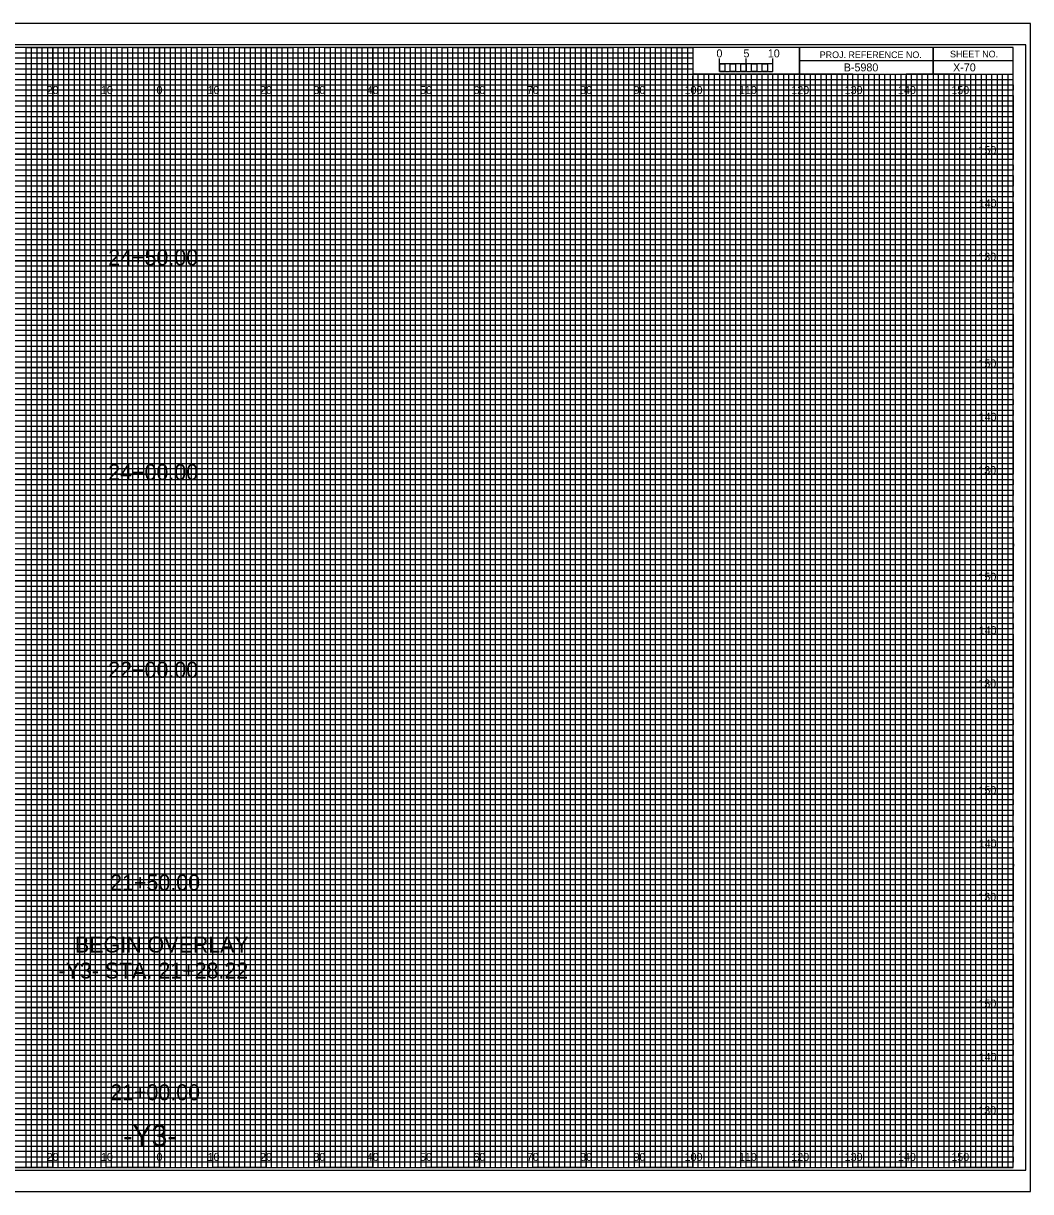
# Model space of a CAD drawing. Extents: x -13 to 323, y -5 to 434.
# Drawn here: x 134.5 to 323.3, y -4.5 to 214.5 of the extents above; entities that cross this region are included whole.
import ezdxf

# ---------------------------------------------------------------- set-up
doc = ezdxf.new("R2010")
doc.units = 0
for name, color, linetype in [('Exist Cross Section Cell', 7, 'Continuous'), ('Exist XS Center Line Elevation Label', 7, 'Continuous'), ('Exist XS Ground Line', 7, 'Continuous'), ('Prop CMT Pvmt Course 1', 7, 'Continuous'), ('Prop CMT Pvmt Course 2', 7, 'Continuous'), ('Prop CMT Pvmt Course 3', 7, 'Continuous'), ('Prop CMT Pvmt Surface', 7, 'Continuous'), ('Prop CMT Pvmt Surface Shoulder', 7, 'Continuous'), ('Prop CMT Shld Paved Course 1', 7, 'Continuous'), ('Prop CMT Shld Paved Course 2', 7, 'Continuous'), ('Prop CMT Shld Paved Course 3', 7, 'Continuous'), ('Prop CMT Slope Grass', 7, 'Continuous'), ('Prop CMT Subgrade Earthwork', 7, 'Continuous'), ('Prop SS Cut Text', 7, 'Continuous'), ('Prop SS Fill Line', 7, 'Continuous'), ('Prop SS Transition Line', 7, 'Continuous'), ('Prop XS Side Slope Text', 7, 'Continuous')]:
    doc.layers.add(name, color=color, linetype=linetype)

msp = doc.modelspace()

# ---------------------------------------------------------------- linework, layer by layer
at = {"layer": 'Exist XS Center Line Elevation Label'}
for points in [[(125, 0), (135, 0), (135, 210), (145, 210), (145, 0), (155, 0), (155, 210), (165, 210), (165, 0), (175, 0), (175, 210), (185, 210), (185, 0), (195, 0), (195, 210), (205, 210), (205, 0), (215, 0), (215, 210), (225, 210), (225, 0), (235, 0), (235, 210), (245, 210), (245, 0), (255, 0), (255, 210), (259.93, 210), (260, 210), (260, 205), (264.99, 205), (264.99, 0), (275, 0), (275, 205), (285, 205), (285, 0), (295, 0), (295, 205), (305, 205), (305, 0), (315, 0), (315, 205)], [(0, 205), (275, 205)], [(0, 185), (320, 185), (320, 195), (0, 195)], [(0, 165), (320, 165), (320, 175), (0, 175)], [(0, 145), (320, 145), (320, 155), (0, 155)], [(0, 125), (320, 125), (320, 135), (0, 135)], [(0, 105), (320, 105), (320, 115), (0, 115)], [(0, 85), (320, 85), (320, 95), (0, 95)], [(0, 65), (320, 65), (320, 75), (0, 75)], [(0, 45), (320, 45), (320, 55), (0, 55)], [(0, 25), (320, 25), (320, 35), (0, 35)], [(0, 5), (320, 5), (320, 15), (0, 15)]]:
    msp.add_lwpolyline(points, dxfattribs=at)
at = {"layer": 'Exist XS Ground Line'}
for p, q in [((150, 210), (140, 210)), ((140, 210), (140, 0)), ((150, 0), (150, 210)), ((170, 210), (160, 210)), ((160, 210), (160, 0)), ((170, 0), (170, 210)), ((190, 210), (180, 210)), ((180, 210), (180, 0)), ((190, 0), (190, 210)), ((210, 210), (200, 210)), ((200, 210), (200, 0)), ((210, 0), (210, 210)), ((230, 210), (220, 210)), ((220, 210), (220, 0)), ((230, 0), (230, 210)), ((250, 210), (240, 210)), ((240, 210), (240, 0)), ((250, 0), (250, 210)), ((260, 210), (260, 0)), ((270, 0), (270, 205)), ((290, 205), (280, 205)), ((280, 205), (280, 0)), ((290, 0), (290, 205)), ((310, 205), (300, 205)), ((300, 205), (300, 0)), ((310, 0), (310, 205)), ((140, 0), (130, 0)), ((160, 0), (150, 0)), ((180, 0), (170, 0)), ((200, 0), (190, 0)), ((220, 0), (210, 0)), ((240, 0), (230, 0)), ((260, 0), (250, 0)), ((280, 0), (270, 0)), ((300, 0), (290, 0)), ((320, 0), (310, 0)), ((320, 0), (320, 0))]:
    msp.add_line(p, q, dxfattribs=at)
for points in [[(0, 200), (320, 200), (320, 190), (0, 190)], [(0, 180), (320, 180), (320, 170), (0, 170)], [(0, 160), (320, 160), (320, 150), (0, 150)], [(0, 140), (320, 140), (320, 130), (0, 130)], [(0, 120), (320, 120), (320, 110), (0, 110)], [(0, 100), (320, 100), (320, 90), (0, 90)], [(0, 80), (320, 80), (320, 70), (0, 70)], [(0, 60), (320, 60), (320, 50), (0, 50)], [(0, 40), (320, 40), (320, 30), (0, 30)], [(0, 20), (320, 20), (320, 10), (0, 10)]]:
    msp.add_lwpolyline(points, dxfattribs=at)
at = {"layer": 'Prop CMT Pvmt Course 1'}
for p, q in [((265, 205.49), (265, 207.9)), ((265, 206.9), (265, 207.9)), ((270, 205.49), (270, 207.9)), ((275, 205.49), (275, 207.9)), ((275, 206.9), (275, 207.9))]:
    msp.add_line(p, q, dxfattribs=at)
for points in [[(275, 206.9), (265, 206.9), (265, 205.49), (275, 205.49)], [(265, 206.9), (266, 206.9), (266, 205.49), (265, 205.49)], [(267, 206.9), (268, 206.9), (268, 205.49), (267, 205.49)], [(269, 206.9), (270, 206.9), (270, 205.49), (269, 205.49)], [(271, 206.9), (272, 206.9), (272, 205.49), (271, 205.49)], [(273, 206.9), (274, 206.9), (274, 205.49), (273, 205.49)]]:
    msp.add_lwpolyline(points, close=True, dxfattribs=at)
at = {"layer": 'Prop CMT Pvmt Course 2'}
for p, q in [((0, 209), (260, 209)), ((260, 209), (260, 207.98)), ((260, 207.98), (0, 207.98)), ((0, 207), (260, 207)), ((260, 205.89), (0, 205.89)), ((260, 207), (260, 205.89)), ((0, 204), (320, 204))]:
    msp.add_line(p, q, dxfattribs=at)
for points in [[(0, 203), (270, 203), (320, 203), (320, 202), (0, 202)], [(0, 201), (320, 201), (320, 199), (0, 199)], [(0, 198), (320, 198), (320, 197), (0, 196.98)], [(0, 196), (320, 196), (320, 194), (0, 194)], [(0, 193), (320, 193), (320, 192), (0, 192)], [(0, 191), (320, 191), (320, 189), (0, 189)], [(0, 188), (320, 188), (320, 187), (0, 187)], [(0, 186), (320, 186), (320, 184), (0, 184)], [(0, 183), (320, 183), (320, 182), (0, 182)], [(0, 181), (320, 181), (320, 179), (0, 179)], [(0, 178), (320, 178), (320, 177), (0, 177)], [(0, 176), (320, 176), (320, 173.95), (320, 173), (320, 172), (0, 172)], [(0, 174), (320, 174), (320, 173), (0, 173)], [(0, 171), (320, 171), (320, 169), (0, 169.03)], [(0, 169.03), (320, 169), (320, 168), (0, 168)], [(0, 167), (320, 167), (320, 166), (0, 166)], [(0, 164), (320, 164), (320, 163), (0, 163)], [(0, 162), (320, 162), (320, 161), (0, 161)], [(-0.07, 158.89), (320, 158.89), (320, 157.88), (-0.07, 157.88)], [(0, 157), (320, 157), (320, 156), (0, 156)], [(0, 154), (320, 154), (320, 153), (0, 153)], [(0, 152), (320, 152), (320, 151), (0, 151)], [(0, 149), (320, 149), (320, 148), (0, 148)], [(0, 147), (320, 147), (320, 146), (0, 146)], [(0, 144), (320, 144), (320, 143), (0, 143)], [(0, 142), (320, 142), (320, 141), (0, 141)], [(0, 139), (320, 139), (319.99, 137.98), (0, 138)], [(0, 137), (320, 137), (320, 136), (0, 136)], [(0, 134), (320, 134), (320, 133), (0, 133)], [(0, 132), (320, 132), (320, 131), (0, 131)], [(0, 129), (320, 129), (320, 128), (0, 128)], [(0, 127), (320, 127), (320, 126), (0, 126)], [(0, 124), (320, 124), (320, 123), (0, 123)], [(0, 122), (320, 122), (320, 121), (0, 121)], [(0, 119), (320, 119), (320, 118), (0, 118)], [(0, 116.99), (320.07, 116.91), (320, 116), (0, 116)], [(0, 114), (320, 114), (320, 113), (0, 113)], [(0, 112), (320, 112), (320, 111), (0, 111)], [(0, 109), (320, 109), (320, 108), (0, 108)], [(0, 107), (320, 107), (320, 106), (0, 106)], [(0, 104), (320, 104), (320, 103), (0, 103)], [(0, 102), (320, 102), (320, 101), (0, 101)], [(0, 99), (320, 99), (320, 98), (0, 98)], [(0, 97), (320, 97), (320, 96), (0, 96)], [(0, 94), (320, 94), (320, 93), (0, 93)], [(0, 92), (320, 92), (320, 91), (0, 91)], [(0, 89), (320, 89), (320, 88), (0, 88)], [(0, 87), (320, 87), (320, 86), (0, 86)], [(0, 84), (320, 84), (320, 83), (0, 83)], [(0, 82), (320, 82), (320, 81), (0, 81)], [(0, 79), (320, 79), (319.99, 77.98), (0, 78)], [(0, 77), (320, 77), (320, 76), (0, 76)], [(0, 74), (320, 74), (320, 73), (0, 73)], [(0, 72), (320, 72), (320, 71), (0, 71)], [(0, 69), (320, 69), (320, 68), (0, 68)], [(0, 67), (320, 67), (320, 66), (0, 66)], [(0, 64), (320, 64), (320, 63), (0, 63)], [(0, 62), (320, 62), (320, 61), (0, 61)], [(0, 59), (320, 59), (320, 58), (0, 58)], [(0, 56.99), (320.07, 56.91), (320, 56), (0, 56)], [(0, 54), (320, 54), (320, 53), (0, 53)], [(0, 52), (320, 52), (320, 51), (0, 51)], [(0, 49), (320, 49), (320, 48), (0, 48)], [(0, 47), (320, 47), (320, 46), (0, 46)], [(0, 44), (320, 44), (320, 43), (0, 43)], [(0, 42), (320, 42), (320, 41), (0, 41)], [(0, 39), (320, 39), (320, 38), (0, 38)], [(0, 37), (320, 37), (320, 36), (0, 36)], [(0, 34), (320, 34), (320, 33), (0, 33)], [(0, 32), (320, 32), (320, 31), (0, 31)], [(0, 29), (320, 29), (320, 28), (0, 28)], [(0, 27), (320, 27), (320, 26), (0, 26)], [(0, 24), (320, 24), (320, 23), (0, 23)], [(0, 22), (320, 22), (320, 21), (0, 21)], [(0, 19), (320, 19), (320, 18), (0, 18)], [(0, 17), (320, 17), (320, 16), (0, 16)], [(0, 14), (320, 14), (320, 13), (0, 13)], [(0, 12), (320, 12), (320, 11), (0, 11)], [(0, 9), (320, 9), (320, 8), (0, 8)], [(0, 7), (320, 7), (320, 6), (0, 6)], [(0, 4), (320, 4), (320, 3), (0, 3)], [(0, 2), (320, 2), (320, 1), (0, 1)]]:
    msp.add_lwpolyline(points, dxfattribs=at)
at = {"layer": 'Prop CMT Pvmt Course 3'}
for p, q in [((305, 210), (305, 205)), ((305, 205), (305, 210)), ((280, 207.5), (280, 205)), ((320, 207.49), (280, 207.49)), ((280, 205), (320, 205))]:
    msp.add_line(p, q, dxfattribs=at)
for points in [[(320, 210), (0, 210), (0, 0), (320, 0)], [(280, 210), (260, 210), (260, 205.03), (280, 205.03)], [(320, 210), (280, 210), (280, 205), (320, 205)]]:
    msp.add_lwpolyline(points, close=True, dxfattribs=at)
at = {"layer": 'Prop CMT Pvmt Surface'}
for p, q in [((267, 205), (266.01, 205)), ((266.01, 205), (266.01, 0)), ((267, 0), (267, 205)), ((269, 205), (268, 205)), ((268, 205), (268, 0)), ((269, 0), (269, 205)), ((266.01, 0), (265, 0)), ((268, 0), (267, 0))]:
    msp.add_line(p, q, dxfattribs=at)
for points in [[(135, 0), (136, 0), (136, 210), (137, 210), (137, 0)], [(137, 0), (138, 0), (138, 210), (139, 210), (139, 0)], [(140, 0), (141, 0), (141, 210), (142, 210), (142, 0)], [(142, 0), (143, 0), (143, 210), (144, 210), (144, 0)], [(145, 0), (146, 0), (146, 210), (147, 210), (147, 0)], [(147, 0), (148, 0), (148, 210), (149, 210), (149, 0)], [(150, 0), (151, 0), (151, 210), (152, 210), (152, 0)], [(152, 0), (153, 0), (153, 210), (154, 210), (154, 0)], [(155, 0), (156, 0), (156, 210), (157, 210), (157, 0)], [(157, 0), (158, 0), (158, 210), (159, 210), (159, 0)], [(160, 0), (161, 0), (161, 210), (162, 210), (162, 0)], [(162, 0), (163, 0), (163, 210), (164, 210), (164, 0)], [(165, 0), (166, 0), (166, 210), (167, 210), (167, 0)], [(167, 0), (168, 0), (168, 210), (169, 210), (169, 0)], [(170, 0), (171, 0), (171, 210), (172, 210), (172, 0)], [(172, 0), (173, 0), (173, 210), (174, 210), (174, 0)], [(175, 0), (176, 0), (176, 210), (177, 210), (177, 0)], [(177, 0), (178, 0), (178, 210), (179, 210), (179, 0)], [(180, 0), (181, 0), (181, 210), (182, 210), (182, 0)], [(182, 0), (183, 0), (183, 210), (184, 210), (184, 0)], [(185, 0), (186, 0), (186, 210), (187, 210), (187, 0)], [(187, 0), (188, 0), (188, 210), (189, 210), (189, 0)], [(190, 0), (191, 0), (191, 210), (192, 210), (192, 0)], [(192, 0), (193, 0), (193, 210), (194, 210), (194, 0)], [(195, 0), (196, 0), (196, 210), (197, 210), (197, 0)], [(197, 0), (198, 0), (198, 210), (199, 210), (199, 0)], [(200, 0), (201, 0), (201, 210), (202, 210), (202, 0)], [(202, 0), (203, 0), (203, 210), (204, 210), (204, 0)], [(205, 0), (206, 0), (206, 210), (207, 210), (207, 0)], [(207, 0), (208, 0), (208, 210), (209, 210), (209, 0)], [(210, 0), (211, 0), (211, 210), (212, 210), (212, 0)], [(212, 0), (213, 0), (213, 210), (214, 210), (214, 0)], [(215, 0), (216, 0), (216, 210), (217, 210), (217, 0)], [(217, 0), (218, 0), (218, 210), (219, 210), (219, 0)], [(220, 0), (221, 0), (221, 210), (222, 210), (222, 0)], [(222, 0), (223, 0), (223, 210), (224, 210), (224, 0)], [(225, 0), (226, 0), (226, 210), (227, 210), (227, 0)], [(227, 0), (228, 0), (228, 210), (229, 210), (229, 0)], [(230, 0), (231, 0), (231, 210), (232, 210), (232, 0)], [(232, 0), (233, 0), (233, 210), (234, 210), (234, 0)], [(235, 0), (236, 0), (236, 210), (237, 210), (237, 0)], [(237, 0), (238, 0), (238, 210), (239, 210), (239, 0)], [(240, 0), (241, 0), (241, 210), (242, 210), (242, 0)], [(242, 0), (243, 0), (243, 210), (244, 210), (244, 0)], [(245, 0), (246, 0), (246, 210), (247, 210), (247, 0)], [(247, 0), (248, 0), (248, 210), (249, 210), (249, 0)], [(250, 0), (251, 0), (251, 210), (252, 210), (252, 0)], [(252, 0), (253, 0), (253, 210), (254, 210), (254, 0)], [(255, 0), (256, 0), (256, 210), (257, 210), (257, 0)], [(257, 0), (258, 0), (258, 210), (259, 210), (259, 0)], [(260, 0), (261, 0), (261, 205), (262.02, 205), (262.02, 0)], [(262, 0), (263, 0), (263, 205), (263.99, 205), (263.99, 0)], [(270, 0), (270.98, 0), (270.98, 205), (272, 205), (272, 0)], [(272, 0), (273, 0), (273, 205), (274.05, 205), (274.05, 0)], [(275, 0), (276, 0), (276, 205), (277, 205), (277, 0)], [(277, 0), (278, 0), (278, 205), (279, 205), (279, 0)], [(280, 0), (281, 0), (281, 205), (282, 205), (282, 0)], [(282, 0), (283, 0), (283, 205), (284, 205), (284, 0)], [(285, 0), (286, 0), (286, 205), (287, 205), (287, 0)], [(287, 0), (288, 0), (288, 205), (289, 205), (289, 0)], [(290, 0), (291, 0), (291, 205), (292, 205), (292, 0)], [(292, 0), (293, 0), (293, 205), (294, 205), (294, 0)], [(295, 0), (296, 0), (296, 205), (297, 205), (297, 0)], [(297, 0), (298, 0), (298, 205), (299, 205), (299, 0)], [(300, 0), (301, 0), (301, 205), (302, 205), (302, 0)], [(302, 0), (303, 0), (303, 205), (304, 205), (304, 0)], [(305, 0), (306, 0), (306, 205), (307, 205), (307, 0)], [(307, 0), (308, 0), (308, 205), (309, 205), (309, 0)], [(310, 0), (311, 0), (311, 205), (312, 205), (312, 0)], [(312, 0), (313, 0), (313, 205), (314, 205), (314, 0)], [(315, 0), (316, 0), (316, 205), (317, 205), (317, 0)], [(317, 0), (318, 0), (318, 205), (319, 205), (319, 0)]]:
    msp.add_lwpolyline(points, dxfattribs=at)
at = {"layer": 'Prop CMT Pvmt Surface Shoulder'}
msp.add_lwpolyline([(-10.8, -0.5), (322.4, -0.5), (322.4, 210.5), (-10.8, 210.5)], close=True, dxfattribs=at)
at = {"layer": 'Prop CMT Shld Paved Course 1'}
for p, q in [((140, 0), (140, 210)), ((150, 0), (150, 210)), ((160, 0), (160, 210)), ((170, 0), (170, 210)), ((180, 0), (180, 210)), ((190, 0), (190, 210)), ((200, 0), (200, 210)), ((210, 0), (210, 210)), ((220, 0), (220, 210)), ((230, 0), (230, 210)), ((240, 0), (240, 210)), ((250, 0), (250, 210)), ((260, 0), (260, 204.69)), ((270, 0), (270, 204.69)), ((280, 0), (280, 204.69)), ((290, 0), (290, 204.69)), ((300, 0), (300, 204.69)), ((310, 0), (310, 204.69)), ((0, 200), (320, 200)), ((0, 190), (320, 190)), ((0, 180), (320, 180)), ((0, 170), (320, 170)), ((0, 160), (320, 160)), ((0, 150), (320, 150)), ((0, 140), (320, 140)), ((0, 130), (320, 130)), ((0, 120), (320, 120)), ((0, 110), (320, 110)), ((0, 100), (320, 100)), ((0, 90), (320, 90)), ((0, 80), (320, 80)), ((0, 70), (320, 70)), ((0, 60), (320, 60)), ((0, 50), (320, 50)), ((0, 40), (320, 40)), ((0, 30), (320, 30)), ((0, 20), (320, 20)), ((0, 10), (320, 10))]:
    msp.add_line(p, q, dxfattribs=at)
at = {"layer": 'Prop CMT Shld Paved Course 2'}
for p, q in [((323.3, 214.5), (-13.4, 214.5)), ((-13.4, -4.5), (323.3, -4.5))]:
    msp.add_line(p, q, dxfattribs=at)
at = {"layer": 'Prop CMT Subgrade Earthwork'}
msp.add_lwpolyline([(-13.4, -4.5), (323.3, -4.5), (323.3, 214.5), (-13.4, 214.5)], close=True, dxfattribs=at)

# ---------------------------------------------------------------- texts
at = {"layer": 'Exist Cross Section Cell'}
for s, p in [('20', (138.86, 201.25)), ('10', (149.04, 201.25)), ('0', (159.45, 201.25)), ('0', (159.45, 201.25)), ('10', (169.04, 201.25)), ('20', (178.86, 201.25)), ('30', (188.86, 201.25)), ('40', (198.86, 201.25)), ('50', (208.86, 201.25)), ('60', (218.86, 201.25)), ('70', (228.86, 201.25)), ('80', (238.86, 201.25)), ('90', (248.86, 201.25)), ('100', (258.44, 201.25)), ('110', (268.62, 201.25)), ('120', (278.44, 201.25)), ('130', (288.44, 201.25)), ('140', (298.44, 201.25)), ('150', (308.44, 201.25)), ('20', (138.86, 1.25)), ('10', (149.04, 1.25)), ('0', (159.45, 1.25)), ('0', (159.45, 1.25)), ('10', (169.04, 1.25)), ('20', (178.86, 1.25)), ('30', (188.86, 1.25)), ('40', (198.86, 1.25)), ('50', (208.86, 1.25)), ('60', (218.86, 1.25)), ('70', (228.86, 1.25)), ('80', (238.86, 1.25)), ('90', (248.86, 1.25)), ('100', (258.44, 1.25)), ('110', (268.62, 1.25)), ('120', (278.44, 1.25)), ('130', (288.44, 1.25)), ('140', (298.44, 1.25)), ('150', (308.44, 1.25))]:
    msp.add_text(s, height=1.5, dxfattribs=at).set_placement(p)
at = {"layer": 'Prop CMT Pvmt Course 1'}
msp.add_text('0', height=1.5, dxfattribs=at).set_placement((264.41, 208.12))
at = {"layer": 'Prop CMT Pvmt Course 3'}
for s, p in [('PROJ. REFERENCE NO.', (283.77, 207.99)), ('SHEET NO.', (308.19, 208.12))]:
    msp.add_text(s, height=1.25, dxfattribs=at).set_placement(p)
at = {"layer": 'Prop CMT Shld Paved Course 3'}
for s, p in [('150', (313.52, 190)), ('140', (313.57, 180)), ('130', (313.49, 170)), ('150', (313.52, 150)), ('140', (313.57, 140)), ('130', (313.49, 130)), ('150', (313.52, 110)), ('140', (313.57, 100)), ('130', (313.49, 90)), ('150', (313.52, 70)), ('140', (313.57, 60)), ('130', (313.49, 50)), ('150', (313.52, 30)), ('140', (313.57, 20)), ('130', (313.49, 10))]:
    msp.add_text(s, height=1.5, dxfattribs=at).set_placement(p)
at = {"layer": 'Prop CMT Slope Grass'}
for s, p in [('24+50.00', (150.41, 169.13)), ('24+00.00', (150.41, 128.88)), ('22+00.00', (150.41, 91.83)), ('21+50.00', (150.77, 51.95)), ('BEGIN OVERLAY', (144.18, 40.32)), ('-Y3- STA. 21+28.22', (141.08, 35.45)), ('21+00.00', (150.77, 12.62))]:
    msp.add_text(s, height=3, dxfattribs=at).set_placement(p)
at = {"layer": 'Prop SS Cut Text'}
msp.add_text('-Y3-', height=4, dxfattribs=at).set_placement((153.17, 4))
at = {"layer": 'Prop SS Fill Line'}
for s, p in [('5', (269.47, 208.12)), ('10', (274.04, 208.12))]:
    msp.add_text(s, height=1.5, dxfattribs=at).set_placement(p)
at = {"layer": 'Prop SS Transition Line'}
msp.add_text('B-5980', height=1.5, dxfattribs=at).set_placement((288.28, 205.5))
at = {"layer": 'Prop XS Side Slope Text'}
msp.add_text('X-70', height=1.5, dxfattribs=at).set_placement((308.77, 205.5))

doc.saveas('drawing.dxf')
